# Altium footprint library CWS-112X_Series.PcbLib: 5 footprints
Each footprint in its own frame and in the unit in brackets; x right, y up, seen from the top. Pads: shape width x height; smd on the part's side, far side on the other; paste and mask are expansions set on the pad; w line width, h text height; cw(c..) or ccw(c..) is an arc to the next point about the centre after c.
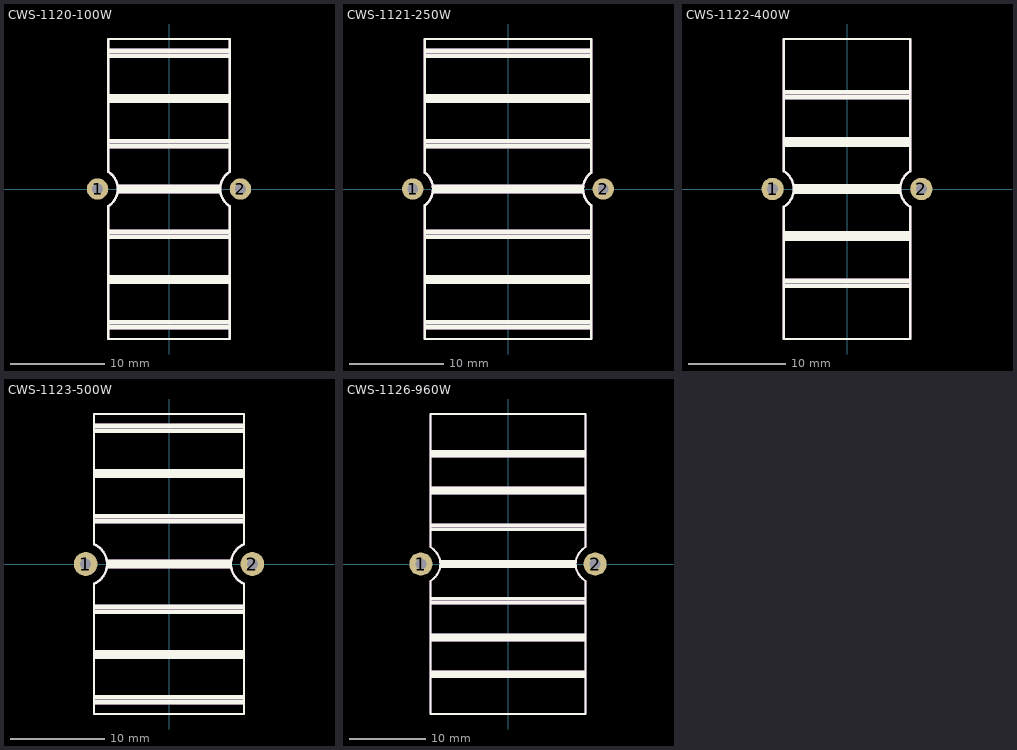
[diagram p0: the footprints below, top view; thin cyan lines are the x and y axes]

## CWS-1120-100W [mil]
pads (2):
  round 90 hole 45: 1(-300,0) 2(300,0)
Top Overlay:
  lines w10: -255.8,-72.61 ccw(c-300,0) -255.35,72.33 ; -255.5,-73.1 -255.5,-630 255,-630 255,-72.61 ; -255.5,72.08 -255.5,630 255,630 ; 255.35,72.33 ccw(c300,0) 255.8,-72.61 ; 255.5,72.33 255.5,630
  lines w19.68: -250,-580 250,-580 ; -250,-560 250,-560 ; -250,-390 250,-390 ; -250,-370 250,-370 ; -250,-200 250,-200 ; -250,-180 250,-180 ; -250,180 250,180 ; -250,200 250,200 ; -250,370 250,370 ; -250,390 250,390 ; -250,560 250,560 ; -250,580 250,580 ; -210,-10 210,-10 ; -210,10 210,10
Mechanical 29:
  lines w10: -255.8,-72.61 ccw(c-300,0) -255.35,72.33 ; -255.5,-73.1 -255.5,-630 255,-630 255,-72.61 ; -255.5,72.08 -255.5,630 255,630 ; 255.35,72.33 ccw(c300,0) 255.8,-72.61 ; 255.5,72.33 255.5,630
  lines w19.68: -250,-580 250,-580 ; -250,-560 250,-560 ; -250,-390 250,-390 ; -250,-370 250,-370 ; -250,-200 250,-200 ; -250,-180 250,-180 ; -250,180 250,180 ; -250,200 250,200 ; -250,370 250,370 ; -250,390 250,390 ; -250,560 250,560 ; -250,580 250,580 ; -210,-10 210,-10 ; -210,10 210,10
  text "'.Designator'" at -1750,-64.85 h400

## CWS-1121-250W [mil]
pads (2):
  round 90 hole 45: 1(-400,0) 2(400,0)
Top Overlay:
  lines w10: -350.2,-68.89 ccw(c-400,0) -350.11,68.82 ; -350,-68.89 -350,-630 350,-630 350,-68.89 ; -350,68.82 -350,630 350,630 350,68.82 ; 350.11,68.82 ccw(c400,0) 350.2,-68.89
  lines w19.68: -345,-580 345,-580 ; -345,-560 345,-560 ; -345,-390 345,-390 ; -345,-370 345,-370 ; -345,-200 345,-200 ; -345,-180 345,-180 ; -345,180 345,180 ; -345,200 345,200 ; -345,370 345,370 ; -345,390 345,390 ; -345,560 345,560 ; -345,580 345,580 ; -310,-10 310,-10 ; -310,10 310,10
Mechanical 29:
  lines w10: -350.2,-68.89 ccw(c-400,0) -350.11,68.82 ; -350,-68.89 -350,-630 350,-630 350,-68.89 ; -350,68.82 -350,630 350,630 350,68.82 ; 350.11,68.82 ccw(c400,0) 350.2,-68.89
  lines w19.68: -345,-580 345,-580 ; -345,-560 345,-560 ; -345,-390 345,-390 ; -345,-370 345,-370 ; -345,-200 345,-200 ; -345,-180 345,-180 ; -345,180 345,180 ; -345,200 345,200 ; -345,370 345,370 ; -345,390 345,390 ; -345,560 345,560 ; -345,580 345,580 ; -310,-10 310,-10 ; -310,10 310,10
  text "'.Designator'" at -1750,-64.85 h400

## CWS-1122-400W [mil]
pads (2):
  round 90 hole 45: 1(-300,0) 2(300,0)
Top Overlay:
  lines w10: -255.5,-605 255,-605 255,-72.08 ; -255.5,605 255,605 255,72.08 ; -255,-605 -255,-72.08 ; -255,72.08 -255,605 ; -254.95,-72.08 ccw(c-300,0) -254.95,72.08 ; 254.95,-72.08 cw(c300,0) 254.95,72.08
  lines w19.68: -250,-390 250,-390 ; -250,-370 250,-370 ; -250,-200 250,-200 ; -250,-180 250,-180 ; -250,180 250,180 ; -250,200 250,200 ; -250,370 250,370 ; -250,390 250,390 ; -210,-10 210,-10 ; -210,10 210,10
Mechanical 29:
  lines w10: -255.5,-605 255,-605 255,-72.08 ; -255.5,605 255,605 255,72.08 ; -255,-605 -255,-72.08 ; -255,72.08 -255,605 ; -254.95,-72.08 ccw(c-300,0) -254.95,72.08 ; 254.95,-72.08 cw(c300,0) 254.95,72.08
  lines w19.68: -250,-390 250,-390 ; -250,-370 250,-370 ; -250,-200 250,-200 ; -250,-180 250,-180 ; -250,180 250,180 ; -250,200 250,200 ; -250,370 250,370 ; -250,390 250,390 ; -210,-10 210,-10 ; -210,10 210,10
  text "'.Designator'" at -1750,-64.85 h400

## CWS-1123-500W [mil]
pads (2):
  round 100 hole 46: 1(-350,0) 2(350,0)
Top Overlay:
  lines w10: -315.11,82.96 cw(c-350,0) -315,-82.92 -315,-630 315,-630 315,-82.92 cw(c350,0) 315.11,82.96 ; -315,82.96 -315,630 315,630 315,83.22
  lines w19.68: -310,-580 310,-580 ; -310,-560 310,-560 ; -310,-390 310,-390 ; -310,-370 310,-370 ; -310,-200 310,-200 ; -310,-180 310,-180 ; -310,180 310,180 ; -310,200 310,200 ; -310,370 310,370 ; -310,390 310,390 ; -310,560 310,560 ; -310,580 310,580 ; -255,-10 255,-10 ; -255,10 255,10
Mechanical 29:
  lines w10: -315.11,82.96 cw(c-350,0) -315,-82.92 -315,-630 315,-630 315,-82.92 cw(c350,0) 315.11,82.96 ; -315,82.96 -315,630 315,630 315,83.22
  lines w19.68: -310,-580 310,-580 ; -310,-560 310,-560 ; -310,-390 310,-390 ; -310,-370 310,-370 ; -310,-200 310,-200 ; -310,-180 310,-180 ; -310,180 310,180 ; -310,200 310,200 ; -310,370 310,370 ; -310,390 310,390 ; -310,560 310,560 ; -310,580 310,580 ; -255,-10 255,-10 ; -255,10 255,10
  text "'.Designator'" at -1750,-64.85 h400

## CWS-1126-960W [mil]
pads (2):
  round 120 hole 56: 1(-450,0) 2(450,0)
Top Overlay:
  lines w10: -400.09,86.65 cw(c-450,0) -400.05,-86.63 ; -400,-86.63 -400,-775 400,-775 400,-86.72 ; -400,86.8 -400,775 400,775 400,86.8 ; 400.05,-86.63 cw(c450,0) 400.35,86.8
  lines w19.68: -395,-580 395,-580 ; -395,-560 395,-560 ; -395,-390 395,-390 ; -395,-370 395,-370 ; -395,-200 395,-200 ; -395,-180 395,-180 ; -395,180 395,180 ; -395,200 395,200 ; -395,370 395,370 ; -395,390 395,390 ; -395,560 395,560 ; -395,580 395,580 ; -345,-10 345,-10 ; -345,10 345,10
Mechanical 29:
  lines w10: -400.09,86.65 cw(c-450,0) -400.05,-86.63 ; -400,-86.63 -400,-775 400,-775 400,-86.72 ; -400,86.8 -400,775 400,775 400,86.8 ; 400.05,-86.63 cw(c450,0) 400.35,86.8
  lines w19.68: -395,-580 395,-580 ; -395,-560 395,-560 ; -395,-390 395,-390 ; -395,-370 395,-370 ; -395,-200 395,-200 ; -395,-180 395,-180 ; -395,180 395,180 ; -395,200 395,200 ; -395,370 395,370 ; -395,390 395,390 ; -395,560 395,560 ; -395,580 395,580 ; -345,-10 345,-10 ; -345,10 345,10
  text "'.Designator'" at -1750,-64.85 h400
